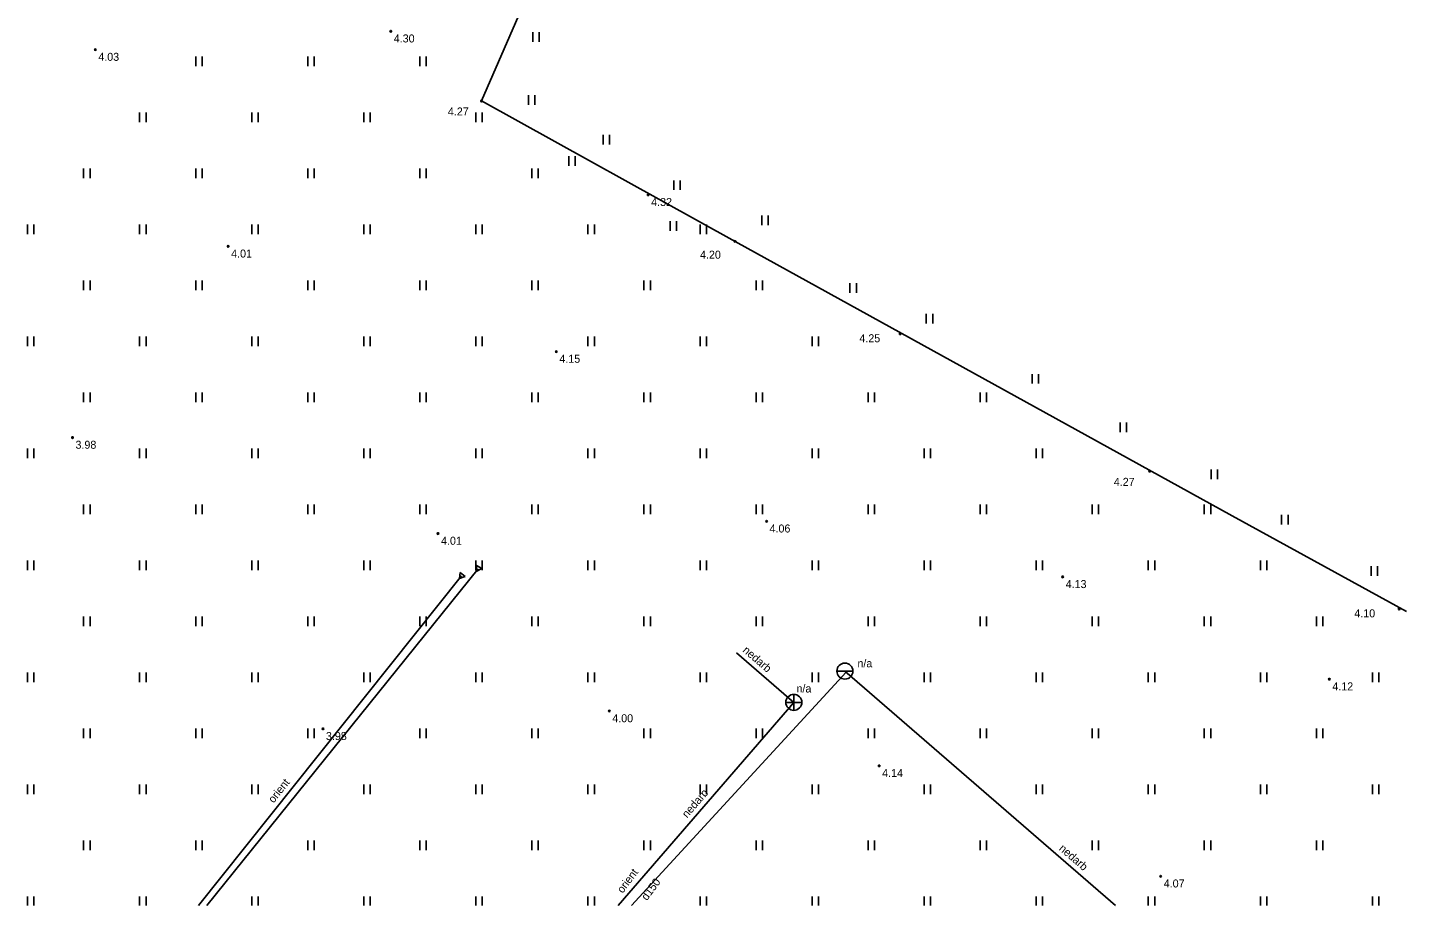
# Model space of a CAD drawing. Extents: x 484635 to 484808, y 278866 to 278977.
# Drawn here: x 484638 to 484724.1, y 278866 to 278920.9 of the extents above; entities that cross this region are included whole.
import ezdxf

# ---------------------------------------------------------------- set-up
doc = ezdxf.new("R2010")
doc.units = 0
for name, color, linetype in [('ELEK_ELEM_####_####_#', 7, 'Continuous'), ('ELEK_VADP_ZSPR_####_#', 7, 'Continuous'), ('ELEK_VADP_ZSPR_TKST_#', 7, 'Continuous'), ('NORB_ZOGS_ZSTP_####_#', 7, 'Continuous'), ('RELJ_AATZ_####_TKST_#', 7, 'Continuous'), ('RELJ_ELEM_####_####_#', 7, 'Continuous'), ('SKAN_ELEM_####_####_#', 7, 'Continuous'), ('SKAN_VADP_NEDR_####_#', 7, 'Continuous'), ('SKAN_VADP_PAST_TKST_#', 7, 'Continuous'), ('TERT_ELEM_####_####_#', 7, 'Continuous'), ('UDTK_ELEM_####_####_#', 7, 'Continuous'), ('UDTK_VADP_NEDR_####_#', 7, 'Continuous'), ('UDTK_VADP_UDEN_TKST_#', 7, 'Continuous')]:
    doc.layers.add(name, color=color, linetype=linetype)

msp = doc.modelspace()

# ---------------------------------------------------------------- linework, layer by layer
at = {"layer": 'ELEK_ELEM_####_####_#'}
for points in [[(484665.334, 278886.607), (484664.977, 278886.482), (484665.021, 278886.857)], [(484665.021, 278886.857), (484665.334, 278886.607)], [(484666.01, 278886.912), (484666.044, 278887.288), (484666.367, 278887.093)], [(484666.367, 278887.093), (484666.01, 278886.912)]]:
    msp.add_lwpolyline(points, dxfattribs=at)
at = {"layer": 'ELEK_VADP_ZSPR_####_#'}
for p, q in [((484665.106, 278886.645), (484648.677, 278866.043)), ((484666.135, 278887.074), (484649.186, 278866.043))]:
    msp.add_line(p, q, dxfattribs=at)
at = {"layer": 'NORB_ZOGS_ZSTP_####_#'}
for p, q in [((484666.355, 278916.319), (484672.607, 278930.737)), ((484682.189, 278907.542), (484666.355, 278916.319)), ((484713.23, 278890.385), (484682.189, 278907.542)), ((484724.123, 278884.403), (484713.23, 278890.385))]:
    msp.add_line(p, q, dxfattribs=at)
at = {"layer": 'RELJ_ELEM_####_####_#'}
for centre in [(484660.686, 278920.677), (484642.232, 278919.528), (484666.355, 278916.319), (484676.764, 278910.455), (484650.529, 278907.233), (484682.189, 278907.542), (484692.5, 278901.767), (484671.029, 278900.657), (484640.807, 278895.284), (484708.087, 278893.182), (484684.158, 278890.051), (484663.639, 278889.285), (484702.653, 278886.577), (484723.673, 278884.576), (484719.311, 278880.184), (484674.334, 278878.191), (484656.45, 278877.081), (484691.192, 278874.769), (484708.779, 278867.868)]:
    msp.add_circle(centre, 0.05, dxfattribs=at)
at = {"layer": 'SKAN_ELEM_####_####_#'}
for p, q in [((484685.86, 278878.236), (484685.86, 278879.236)), ((484685.36, 278878.736), (484686.36, 278878.736))]:
    msp.add_line(p, q, dxfattribs=at)
msp.add_circle((484685.86, 278878.736), 0.5, dxfattribs=at)
at = {"layer": 'SKAN_VADP_NEDR_####_#'}
msp.add_lwpolyline([(484674.887, 278866.043), (484685.864, 278878.733), (484682.28, 278881.833)], dxfattribs=at)
at = {"layer": 'TERT_ELEM_####_####_#'}
for p, q in [((484669.555, 278920.022), (484669.555, 278920.622)), ((484669.955, 278920.022), (484669.955, 278920.622)), ((484648.5, 278918.5), (484648.5, 278919.1)), ((484648.9, 278918.5), (484648.9, 278919.1)), ((484655.5, 278918.5), (484655.5, 278919.1)), ((484655.9, 278918.5), (484655.9, 278919.1)), ((484662.5, 278918.5), (484662.5, 278919.1)), ((484662.9, 278918.5), (484662.9, 278919.1)), ((484669.279, 278916.078), (484669.279, 278916.678)), ((484669.679, 278916.078), (484669.679, 278916.678)), ((484645, 278915), (484645, 278915.6)), ((484645.4, 278915), (484645.4, 278915.6)), ((484652, 278915), (484652, 278915.6)), ((484652.4, 278915), (484652.4, 278915.6)), ((484659, 278915), (484659, 278915.6)), ((484659.4, 278915), (484659.4, 278915.6)), ((484666, 278915), (484666, 278915.6)), ((484666.4, 278915), (484666.4, 278915.6)), ((484673.957, 278913.602), (484673.957, 278914.202)), ((484674.357, 278913.602), (484674.357, 278914.202)), ((484671.808, 278912.271), (484671.808, 278912.871)), ((484672.208, 278912.271), (484672.208, 278912.871)), ((484641.5, 278911.5), (484641.5, 278912.1)), ((484641.9, 278911.5), (484641.9, 278912.1)), ((484648.5, 278911.5), (484648.5, 278912.1)), ((484648.9, 278911.5), (484648.9, 278912.1)), ((484655.5, 278911.5), (484655.5, 278912.1)), ((484655.9, 278911.5), (484655.9, 278912.1)), ((484662.5, 278911.5), (484662.5, 278912.1)), ((484662.9, 278911.5), (484662.9, 278912.1)), ((484669.5, 278911.5), (484669.5, 278912.1)), ((484669.9, 278911.5), (484669.9, 278912.1)), ((484678.359, 278910.759), (484678.359, 278911.359)), ((484678.759, 278910.759), (484678.759, 278911.359)), ((484683.862, 278908.557), (484683.862, 278909.157)), ((484684.262, 278908.557), (484684.262, 278909.157)), ((484638, 278908), (484638, 278908.6)), ((484638.4, 278908), (484638.4, 278908.6)), ((484645, 278908), (484645, 278908.6)), ((484645.4, 278908), (484645.4, 278908.6)), ((484652, 278908), (484652, 278908.6)), ((484652.4, 278908), (484652.4, 278908.6)), ((484659, 278908), (484659, 278908.6)), ((484659.4, 278908), (484659.4, 278908.6)), ((484666, 278908), (484666, 278908.6)), ((484666.4, 278908), (484666.4, 278908.6)), ((484673, 278908), (484673, 278908.6)), ((484673.4, 278908), (484673.4, 278908.6)), ((484678.13, 278908.199), (484678.13, 278908.799)), ((484678.53, 278908.199), (484678.53, 278908.799)), ((484680, 278908), (484680, 278908.6)), ((484680.4, 278908), (484680.4, 278908.6)), ((484641.5, 278904.5), (484641.5, 278905.1)), ((484641.9, 278904.5), (484641.9, 278905.1)), ((484648.5, 278904.5), (484648.5, 278905.1)), ((484648.9, 278904.5), (484648.9, 278905.1)), ((484655.5, 278904.5), (484655.5, 278905.1)), ((484655.9, 278904.5), (484655.9, 278905.1)), ((484662.5, 278904.5), (484662.5, 278905.1)), ((484662.9, 278904.5), (484662.9, 278905.1)), ((484669.5, 278904.5), (484669.5, 278905.1)), ((484669.9, 278904.5), (484669.9, 278905.1)), ((484676.5, 278904.5), (484676.5, 278905.1)), ((484676.9, 278904.5), (484676.9, 278905.1)), ((484683.5, 278904.5), (484683.5, 278905.1)), ((484683.9, 278904.5), (484683.9, 278905.1)), ((484689.365, 278904.338), (484689.365, 278904.938)), ((484689.765, 278904.338), (484689.765, 278904.938)), ((484694.135, 278902.412), (484694.135, 278903.012)), ((484694.535, 278902.412), (484694.535, 278903.012)), ((484638, 278901), (484638, 278901.6)), ((484638.4, 278901), (484638.4, 278901.6)), ((484645, 278901), (484645, 278901.6)), ((484645.4, 278901), (484645.4, 278901.6)), ((484652, 278901), (484652, 278901.6)), ((484652.4, 278901), (484652.4, 278901.6)), ((484659, 278901), (484659, 278901.6)), ((484659.4, 278901), (484659.4, 278901.6)), ((484666, 278901), (484666, 278901.6)), ((484666.4, 278901), (484666.4, 278901.6)), ((484673, 278901), (484673, 278901.6)), ((484673.4, 278901), (484673.4, 278901.6)), ((484680, 278901), (484680, 278901.6)), ((484680.4, 278901), (484680.4, 278901.6)), ((484687, 278901), (484687, 278901.6)), ((484687.4, 278901), (484687.4, 278901.6)), ((484700.738, 278898.652), (484700.738, 278899.252)), ((484701.138, 278898.652), (484701.138, 278899.252)), ((484641.5, 278897.5), (484641.5, 278898.1)), ((484641.9, 278897.5), (484641.9, 278898.1)), ((484648.5, 278897.5), (484648.5, 278898.1)), ((484648.9, 278897.5), (484648.9, 278898.1)), ((484655.5, 278897.5), (484655.5, 278898.1)), ((484655.9, 278897.5), (484655.9, 278898.1)), ((484662.5, 278897.5), (484662.5, 278898.1)), ((484662.9, 278897.5), (484662.9, 278898.1)), ((484669.5, 278897.5), (484669.5, 278898.1)), ((484669.9, 278897.5), (484669.9, 278898.1)), ((484676.5, 278897.5), (484676.5, 278898.1)), ((484676.9, 278897.5), (484676.9, 278898.1)), ((484683.5, 278897.5), (484683.5, 278898.1)), ((484683.9, 278897.5), (484683.9, 278898.1)), ((484690.5, 278897.5), (484690.5, 278898.1)), ((484690.9, 278897.5), (484690.9, 278898.1)), ((484697.5, 278897.5), (484697.5, 278898.1)), ((484697.9, 278897.5), (484697.9, 278898.1)), ((484706.241, 278895.625), (484706.241, 278896.225)), ((484706.641, 278895.625), (484706.641, 278896.225)), ((484638, 278894), (484638, 278894.6)), ((484638.4, 278894), (484638.4, 278894.6)), ((484645, 278894), (484645, 278894.6)), ((484645.4, 278894), (484645.4, 278894.6)), ((484652, 278894), (484652, 278894.6)), ((484652.4, 278894), (484652.4, 278894.6)), ((484659, 278894), (484659, 278894.6)), ((484659.4, 278894), (484659.4, 278894.6)), ((484666, 278894), (484666, 278894.6)), ((484666.4, 278894), (484666.4, 278894.6)), ((484673, 278894), (484673, 278894.6)), ((484673.4, 278894), (484673.4, 278894.6)), ((484680, 278894), (484680, 278894.6)), ((484680.4, 278894), (484680.4, 278894.6)), ((484687, 278894), (484687, 278894.6)), ((484687.4, 278894), (484687.4, 278894.6)), ((484694, 278894), (484694, 278894.6)), ((484694.4, 278894), (484694.4, 278894.6)), ((484701, 278894), (484701, 278894.6)), ((484701.4, 278894), (484701.4, 278894.6)), ((484711.928, 278892.69), (484711.928, 278893.29)), ((484712.328, 278892.69), (484712.328, 278893.29)), ((484641.5, 278890.5), (484641.5, 278891.1)), ((484641.9, 278890.5), (484641.9, 278891.1)), ((484648.5, 278890.5), (484648.5, 278891.1)), ((484648.9, 278890.5), (484648.9, 278891.1)), ((484655.5, 278890.5), (484655.5, 278891.1)), ((484655.9, 278890.5), (484655.9, 278891.1)), ((484662.5, 278890.5), (484662.5, 278891.1)), ((484662.9, 278890.5), (484662.9, 278891.1)), ((484669.5, 278890.5), (484669.5, 278891.1)), ((484669.9, 278890.5), (484669.9, 278891.1)), ((484676.5, 278890.5), (484676.5, 278891.1)), ((484676.9, 278890.5), (484676.9, 278891.1)), ((484683.5, 278890.5), (484683.5, 278891.1)), ((484683.9, 278890.5), (484683.9, 278891.1)), ((484690.5, 278890.5), (484690.5, 278891.1)), ((484690.9, 278890.5), (484690.9, 278891.1)), ((484697.5, 278890.5), (484697.5, 278891.1)), ((484697.9, 278890.5), (484697.9, 278891.1)), ((484704.5, 278890.5), (484704.5, 278891.1)), ((484704.9, 278890.5), (484704.9, 278891.1)), ((484711.5, 278890.5), (484711.5, 278891.1)), ((484711.9, 278890.5), (484711.9, 278891.1)), ((484716.33, 278889.847), (484716.33, 278890.447)), ((484716.73, 278889.847), (484716.73, 278890.447)), ((484638, 278887), (484638, 278887.6)), ((484638.4, 278887), (484638.4, 278887.6)), ((484645, 278887), (484645, 278887.6)), ((484645.4, 278887), (484645.4, 278887.6)), ((484652, 278887), (484652, 278887.6)), ((484652.4, 278887), (484652.4, 278887.6)), ((484659, 278887), (484659, 278887.6)), ((484659.4, 278887), (484659.4, 278887.6)), ((484666, 278887), (484666, 278887.6)), ((484666.4, 278887), (484666.4, 278887.6)), ((484673, 278887), (484673, 278887.6)), ((484673.4, 278887), (484673.4, 278887.6)), ((484680, 278887), (484680, 278887.6)), ((484680.4, 278887), (484680.4, 278887.6)), ((484687, 278887), (484687, 278887.6)), ((484687.4, 278887), (484687.4, 278887.6)), ((484694, 278887), (484694, 278887.6)), ((484694.4, 278887), (484694.4, 278887.6)), ((484701, 278887), (484701, 278887.6)), ((484701.4, 278887), (484701.4, 278887.6)), ((484708, 278887), (484708, 278887.6)), ((484708.4, 278887), (484708.4, 278887.6)), ((484715, 278887), (484715, 278887.6)), ((484715.4, 278887), (484715.4, 278887.6)), ((484721.925, 278886.637), (484721.925, 278887.237)), ((484722.325, 278886.637), (484722.325, 278887.237)), ((484641.5, 278883.5), (484641.5, 278884.1)), ((484641.9, 278883.5), (484641.9, 278884.1)), ((484648.5, 278883.5), (484648.5, 278884.1)), ((484648.9, 278883.5), (484648.9, 278884.1)), ((484655.5, 278883.5), (484655.5, 278884.1)), ((484655.9, 278883.5), (484655.9, 278884.1)), ((484662.5, 278883.5), (484662.5, 278884.1)), ((484662.9, 278883.5), (484662.9, 278884.1)), ((484669.5, 278883.5), (484669.5, 278884.1)), ((484669.9, 278883.5), (484669.9, 278884.1)), ((484676.5, 278883.5), (484676.5, 278884.1)), ((484676.9, 278883.5), (484676.9, 278884.1)), ((484683.5, 278883.5), (484683.5, 278884.1)), ((484683.9, 278883.5), (484683.9, 278884.1)), ((484690.5, 278883.5), (484690.5, 278884.1)), ((484690.9, 278883.5), (484690.9, 278884.1)), ((484697.5, 278883.5), (484697.5, 278884.1)), ((484697.9, 278883.5), (484697.9, 278884.1)), ((484704.5, 278883.5), (484704.5, 278884.1)), ((484704.9, 278883.5), (484704.9, 278884.1)), ((484711.5, 278883.5), (484711.5, 278884.1)), ((484711.9, 278883.5), (484711.9, 278884.1)), ((484718.5, 278883.5), (484718.5, 278884.1)), ((484718.9, 278883.5), (484718.9, 278884.1)), ((484638, 278880), (484638, 278880.6)), ((484638.4, 278880), (484638.4, 278880.6)), ((484645, 278880), (484645, 278880.6)), ((484645.4, 278880), (484645.4, 278880.6)), ((484652, 278880), (484652, 278880.6)), ((484652.4, 278880), (484652.4, 278880.6)), ((484659, 278880), (484659, 278880.6)), ((484659.4, 278880), (484659.4, 278880.6)), ((484666, 278880), (484666, 278880.6)), ((484666.4, 278880), (484666.4, 278880.6)), ((484673, 278880), (484673, 278880.6)), ((484673.4, 278880), (484673.4, 278880.6)), ((484680, 278880), (484680, 278880.6)), ((484680.4, 278880), (484680.4, 278880.6)), ((484687, 278880), (484687, 278880.6)), ((484687.4, 278880), (484687.4, 278880.6)), ((484694, 278880), (484694, 278880.6)), ((484694.4, 278880), (484694.4, 278880.6)), ((484701, 278880), (484701, 278880.6)), ((484701.4, 278880), (484701.4, 278880.6)), ((484708, 278880), (484708, 278880.6)), ((484708.4, 278880), (484708.4, 278880.6)), ((484715, 278880), (484715, 278880.6)), ((484715.4, 278880), (484715.4, 278880.6)), ((484722, 278880), (484722, 278880.6)), ((484722.4, 278880), (484722.4, 278880.6)), ((484641.5, 278876.5), (484641.5, 278877.1)), ((484641.9, 278876.5), (484641.9, 278877.1)), ((484648.5, 278876.5), (484648.5, 278877.1)), ((484648.9, 278876.5), (484648.9, 278877.1)), ((484655.5, 278876.5), (484655.5, 278877.1)), ((484655.9, 278876.5), (484655.9, 278877.1)), ((484662.5, 278876.5), (484662.5, 278877.1)), ((484662.9, 278876.5), (484662.9, 278877.1)), ((484669.5, 278876.5), (484669.5, 278877.1)), ((484669.9, 278876.5), (484669.9, 278877.1)), ((484676.5, 278876.5), (484676.5, 278877.1)), ((484676.9, 278876.5), (484676.9, 278877.1)), ((484683.5, 278876.5), (484683.5, 278877.1)), ((484683.9, 278876.5), (484683.9, 278877.1)), ((484690.5, 278876.5), (484690.5, 278877.1)), ((484690.9, 278876.5), (484690.9, 278877.1)), ((484697.5, 278876.5), (484697.5, 278877.1)), ((484697.9, 278876.5), (484697.9, 278877.1)), ((484704.5, 278876.5), (484704.5, 278877.1)), ((484704.9, 278876.5), (484704.9, 278877.1)), ((484711.5, 278876.5), (484711.5, 278877.1)), ((484711.9, 278876.5), (484711.9, 278877.1)), ((484718.5, 278876.5), (484718.5, 278877.1)), ((484718.9, 278876.5), (484718.9, 278877.1)), ((484638, 278873), (484638, 278873.6)), ((484638.4, 278873), (484638.4, 278873.6)), ((484645, 278873), (484645, 278873.6)), ((484645.4, 278873), (484645.4, 278873.6)), ((484652, 278873), (484652, 278873.6)), ((484652.4, 278873), (484652.4, 278873.6)), ((484659, 278873), (484659, 278873.6)), ((484659.4, 278873), (484659.4, 278873.6)), ((484666, 278873), (484666, 278873.6)), ((484666.4, 278873), (484666.4, 278873.6)), ((484673, 278873), (484673, 278873.6)), ((484673.4, 278873), (484673.4, 278873.6)), ((484680, 278873), (484680, 278873.6)), ((484680.4, 278873), (484680.4, 278873.6)), ((484687, 278873), (484687, 278873.6)), ((484687.4, 278873), (484687.4, 278873.6)), ((484694, 278873), (484694, 278873.6)), ((484694.4, 278873), (484694.4, 278873.6)), ((484701, 278873), (484701, 278873.6)), ((484701.4, 278873), (484701.4, 278873.6)), ((484708, 278873), (484708, 278873.6)), ((484708.4, 278873), (484708.4, 278873.6)), ((484715, 278873), (484715, 278873.6)), ((484715.4, 278873), (484715.4, 278873.6)), ((484722, 278873), (484722, 278873.6)), ((484722.4, 278873), (484722.4, 278873.6)), ((484641.5, 278869.5), (484641.5, 278870.1)), ((484641.9, 278869.5), (484641.9, 278870.1)), ((484648.5, 278869.5), (484648.5, 278870.1)), ((484648.9, 278869.5), (484648.9, 278870.1)), ((484655.5, 278869.5), (484655.5, 278870.1)), ((484655.9, 278869.5), (484655.9, 278870.1)), ((484662.5, 278869.5), (484662.5, 278870.1)), ((484662.9, 278869.5), (484662.9, 278870.1)), ((484669.5, 278869.5), (484669.5, 278870.1)), ((484669.9, 278869.5), (484669.9, 278870.1)), ((484676.5, 278869.5), (484676.5, 278870.1)), ((484676.9, 278869.5), (484676.9, 278870.1)), ((484683.5, 278869.5), (484683.5, 278870.1)), ((484683.9, 278869.5), (484683.9, 278870.1)), ((484690.5, 278869.5), (484690.5, 278870.1)), ((484690.9, 278869.5), (484690.9, 278870.1)), ((484697.5, 278869.5), (484697.5, 278870.1)), ((484697.9, 278869.5), (484697.9, 278870.1)), ((484704.5, 278869.5), (484704.5, 278870.1)), ((484704.9, 278869.5), (484704.9, 278870.1)), ((484711.5, 278869.5), (484711.5, 278870.1)), ((484711.9, 278869.5), (484711.9, 278870.1)), ((484718.5, 278869.5), (484718.5, 278870.1)), ((484718.9, 278869.5), (484718.9, 278870.1)), ((484638, 278866.043), (484638, 278866.6)), ((484638.4, 278866.043), (484638.4, 278866.6)), ((484645, 278866.043), (484645, 278866.6)), ((484645.4, 278866.043), (484645.4, 278866.6)), ((484652, 278866.043), (484652, 278866.6)), ((484652.4, 278866.043), (484652.4, 278866.6)), ((484659, 278866.043), (484659, 278866.6)), ((484659.4, 278866.043), (484659.4, 278866.6)), ((484666, 278866.043), (484666, 278866.6)), ((484666.4, 278866.043), (484666.4, 278866.6)), ((484673, 278866.043), (484673, 278866.6)), ((484673.4, 278866.043), (484673.4, 278866.6)), ((484680, 278866.043), (484680, 278866.6)), ((484680.4, 278866.043), (484680.4, 278866.6)), ((484687, 278866.043), (484687, 278866.6)), ((484687.4, 278866.043), (484687.4, 278866.6)), ((484694, 278866.043), (484694, 278866.6)), ((484694.4, 278866.043), (484694.4, 278866.6)), ((484701, 278866.043), (484701, 278866.6)), ((484701.4, 278866.043), (484701.4, 278866.6)), ((484708, 278866.043), (484708, 278866.6)), ((484708.4, 278866.043), (484708.4, 278866.6)), ((484715, 278866.043), (484715, 278866.6)), ((484715.4, 278866.043), (484715.4, 278866.6)), ((484722, 278866.043), (484722, 278866.6)), ((484722.4, 278866.043), (484722.4, 278866.6))]:
    msp.add_line(p, q, dxfattribs=at)
at = {"layer": 'UDTK_ELEM_####_####_#'}
msp.add_line((484688.552, 278880.689), (484689.552, 278880.689), dxfattribs=at)
msp.add_circle((484689.052, 278880.689), 0.5, dxfattribs=at)
at = {"layer": 'UDTK_VADP_NEDR_####_#'}
msp.add_line((484675.728, 278866.043), (484689.123, 278880.626), dxfattribs=at)
msp.add_lwpolyline([(484689.051, 278880.69), (484689.195, 278880.562), (484705.958, 278866.043)], dxfattribs=at)

# ---------------------------------------------------------------- texts
at = {"layer": 'ELEK_VADP_ZSPR_TKST_#'}
msp.add_text('orient', height=0.5, rotation=51.42969, dxfattribs=at).set_placement((484653.366, 278872.404))
at = {"layer": 'RELJ_AATZ_####_TKST_#'}
for s, p in [(' 4.30', (484660.686, 278919.977)), (' 4.03', (484642.232, 278918.828)), (' 4.27', (484664.067, 278915.413)), (' 4.32', (484676.764, 278909.755)), (' 4.01', (484650.529, 278906.533)), (' 4.20', (484679.816, 278906.462)), (' 4.25', (484689.77, 278901.24)), (' 4.15', (484671.029, 278899.957)), (' 3.98', (484640.807, 278894.584)), (' 4.27', (484705.661, 278892.265)), (' 4.06', (484684.158, 278889.351)), (' 4.01', (484663.639, 278888.585)), (' 4.13', (484702.653, 278885.877)), (' 4.10', (484720.684, 278884.049)), (' 4.12', (484719.311, 278879.484)), (' 4.00', (484674.334, 278877.491)), (' 3.98', (484656.45, 278876.381)), (' 4.14', (484691.192, 278874.069)), (' 4.07', (484708.779, 278867.168))]:
    msp.add_text(s, height=0.5, dxfattribs=at).set_placement(p)
at = {"layer": 'SKAN_VADP_PAST_TKST_#'}
for s, rotation, p in [('nedarb', 319.13821, (484682.627, 278881.93)), ('nedarb', 49.13821, (484679.192, 278871.478)), ('orient', 53.34564, (484675.168, 278866.767)), ('d150', 53.34564, (484676.681, 278866.312))]:
    msp.add_text(s, height=0.5, rotation=rotation, dxfattribs=at).set_placement(p)
msp.add_text('n/a', height=0.5, dxfattribs=at).set_placement((484686.026, 278879.352))
at = {"layer": 'UDTK_VADP_UDEN_TKST_#'}
msp.add_text('n/a', height=0.5, dxfattribs=at).set_placement((484689.834, 278880.925))
msp.add_text('nedarb', height=0.5, rotation=319.10393, dxfattribs=at).set_placement((484702.382, 278869.539))

doc.saveas('drawing.dxf')
